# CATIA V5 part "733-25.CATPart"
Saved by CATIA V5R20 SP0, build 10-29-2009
Part number: 733-25
Bounding box of the stored display mesh (mm): x -24 to 24, y -23.94 to 23.94, z -23 to 56
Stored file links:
  C:\Users\Utente\Desktop\IO LAVORO\3D X SITO CF\X SITO\733\733-25.CATPart
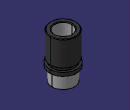
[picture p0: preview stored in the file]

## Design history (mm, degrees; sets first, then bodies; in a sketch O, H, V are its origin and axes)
Set1
  DatumSurface1 to DatumSurface25 "733-25"
Body1 (main body)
